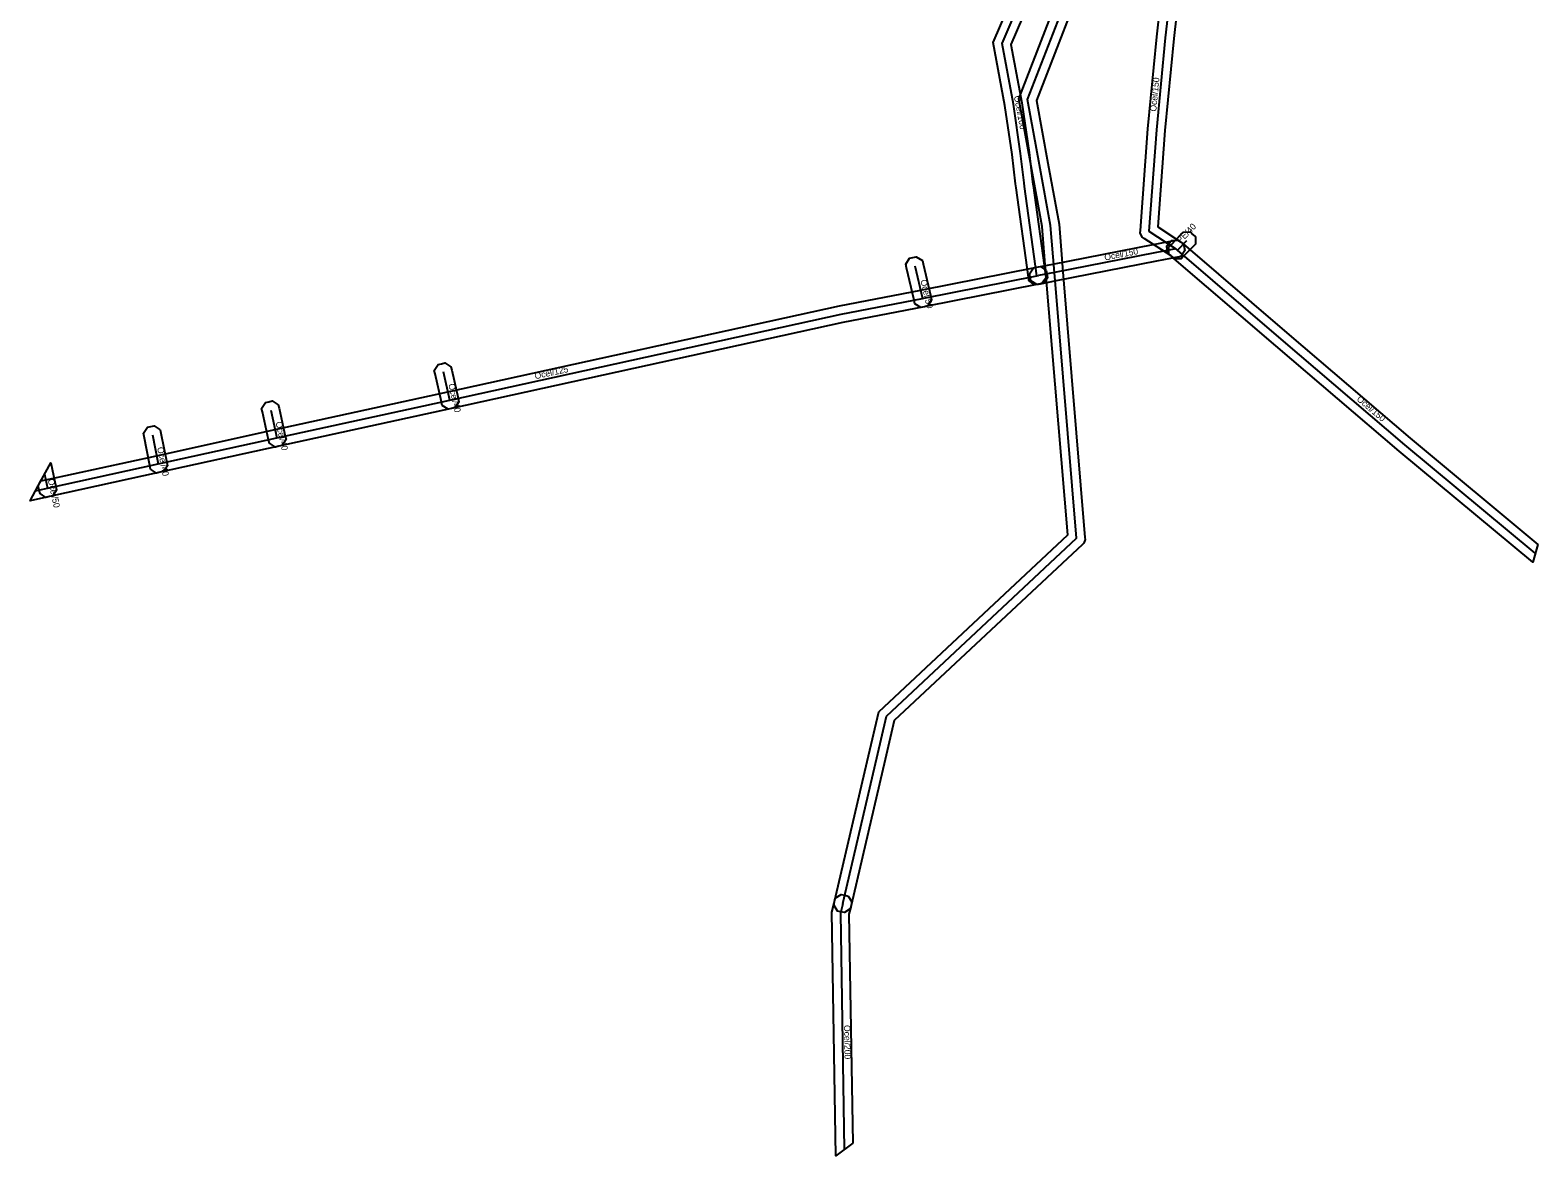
# Model space of a CAD drawing. Extents: x -702919 to -702657, y -1012371 to -1012107.
# Drawn here: x -702887.5 to -702710.5, y -1012371 to -1012238.8 of the extents above; entities that cross this region are included whole.
import ezdxf

# ---------------------------------------------------------------- set-up
doc = ezdxf.new("R2010")
doc.units = 0
for name, color, linetype in [('1', 7, 'Continuous'), ('14', 7, 'Continuous'), ('20', 7, 'Continuous'), ('24', 7, 'Continuous'), ('30', 7, 'Continuous')]:
    doc.layers.add(name, color=color, linetype=linetype)

msp = doc.modelspace()

# ---------------------------------------------------------------- linework, layer by layer
at = {"layer": '1'}
for points in [[(-702762.96, -1012230.4), (-702769.42, -1012247.1), (-702768.08, -1012254.47), (-702766.76, -1012261.63), (-702766.3, -1012267.22), (-702763.71, -1012298.39), (-702763.69, -1012298.62), (-702763.86, -1012299.05), (-702764.02, -1012299.21), (-702786.1, -1012319.9), (-702787.17, -1012324.48), (-702791.17, -1012341.59), (-702791.26, -1012342), (-702791.96, -1012342.44), (-702792.37, -1012342.34), (-702792.77, -1012342.25), (-702793.21, -1012341.54), (-702793.11, -1012341.14), (-702789.12, -1012324.02), (-702787.91, -1012318.85), (-702765.74, -1012298.08), (-702768.29, -1012267.38), (-702768.74, -1012261.89), (-702770.04, -1012254.83), (-702771.48, -1012246.91), (-702764.83, -1012229.68)], [(-702770.32, -1012235.65), (-702772.41, -1012240.53), (-702771.13, -1012247.37), (-702770.28, -1012253.19), (-702769.86, -1012256.65), (-702769.81, -1012257.09), (-702768.36, -1012267.57), (-702768.3, -1012267.98), (-702768.8, -1012268.64), (-702769.21, -1012268.69), (-702769.62, -1012268.75), (-702770.29, -1012268.25), (-702770.34, -1012267.84), (-702771.8, -1012257.34), (-702771.85, -1012256.88), (-702772.26, -1012253.46), (-702773.11, -1012247.7), (-702774.49, -1012240.3), (-702772.15, -1012234.82)]]:
    msp.add_lwpolyline(points, dxfattribs=at)
for points in [[(-702752.25, -1012230.69), (-702752.3, -1012231.1), (-702753.29, -1012239.84), (-702754.33, -1012250.62), (-702755.17, -1012261.94), (-702752.51, -1012263.68), (-702752.16, -1012263.91), (-702751.99, -1012264.72), (-702752.22, -1012265.06), (-702752.45, -1012265.41), (-702753.26, -1012265.58), (-702753.6, -1012265.35), (-702756.76, -1012263.29), (-702756.99, -1012263.14), (-702757.23, -1012262.65), (-702757.21, -1012262.38), (-702756.33, -1012250.45), (-702755.28, -1012239.63), (-702754.28, -1012230.88), (-702754.24, -1012230.46), (-702753.59, -1012229.95), (-702753.18, -1012230), (-702752.77, -1012230.04)], [(-702753.86, -1012264.29), (-702753.57, -1012263.99), (-702752.45, -1012262.84), (-702752.16, -1012262.55), (-702751.33, -1012262.54), (-702751.04, -1012262.83), (-702750.74, -1012263.12), (-702750.73, -1012263.95), (-702751.02, -1012264.24), (-702752.14, -1012265.39), (-702752.43, -1012265.68), (-702753.26, -1012265.69), (-702753.55, -1012265.4), (-702753.85, -1012265.11)], [(-702752.46, -1012265.42), (-702752.86, -1012265.5), (-702755.31, -1012265.97), (-702767.09, -1012268.28), (-702768.97, -1012268.65), (-702769.37, -1012268.72), (-702770.06, -1012268.26), (-702770.14, -1012267.85), (-702770.22, -1012267.45), (-702769.76, -1012266.76), (-702769.35, -1012266.68), (-702767.47, -1012266.32), (-702755.7, -1012264.01), (-702753.25, -1012263.53), (-702752.84, -1012263.45), (-702752.16, -1012263.92), (-702752.08, -1012264.32), (-702752, -1012264.73)], [(-702725.52, -1012286.74), (-702710.54, -1012299.21), (-702711.15, -1012301.31), (-702726.81, -1012288.27), (-702741.31, -1012275.89), (-702753.51, -1012265.45), (-702753.71, -1012265.28), (-702754.02, -1012265.01), (-702754.09, -1012264.18), (-702753.82, -1012263.86), (-702753.55, -1012263.55), (-702752.72, -1012263.49), (-702752.41, -1012263.76), (-702752.2, -1012263.93), (-702740.01, -1012274.37)], [(-702782.8, -1012265.88), (-702782.71, -1012266.28), (-702781.82, -1012270.11), (-702781.72, -1012270.51), (-702782.16, -1012271.21), (-702782.56, -1012271.31), (-702782.97, -1012271.4), (-702783.67, -1012270.96), (-702783.77, -1012270.56), (-702784.66, -1012266.73), (-702784.75, -1012266.33), (-702784.31, -1012265.63), (-702783.91, -1012265.53), (-702783.51, -1012265.44)], [(-702885.29, -1012293.6), (-702887.55, -1012294.1), (-702886.29, -1012291.77), (-702885.72, -1012291.65), (-702872.71, -1012288.8), (-702858.78, -1012285.74), (-702838.5, -1012281.3), (-702792.54, -1012271.22), (-702782.98, -1012269.35), (-702782.83, -1012269.32), (-702769.55, -1012266.72), (-702769.36, -1012266.68), (-702768.95, -1012266.6), (-702768.26, -1012267.06), (-702768.18, -1012267.47), (-702768.1, -1012267.87), (-702768.55, -1012268.56), (-702768.96, -1012268.64), (-702769.16, -1012268.68), (-702782.45, -1012271.29), (-702782.6, -1012271.31), (-702792.13, -1012273.18), (-702838.07, -1012283.25), (-702858.35, -1012287.7), (-702872.29, -1012290.75)], [(-702839.17, -1012282.9), (-702839.26, -1012282.49), (-702840.01, -1012279.19), (-702840.1, -1012278.79), (-702839.66, -1012278.09), (-702839.26, -1012278), (-702838.85, -1012277.91), (-702838.15, -1012278.35), (-702838.06, -1012278.75), (-702837.31, -1012282.05), (-702837.22, -1012282.46), (-702837.66, -1012283.16), (-702838.07, -1012283.25), (-702838.47, -1012283.34)], [(-702858.42, -1012282.82), (-702858.33, -1012283.22), (-702857.59, -1012286.5), (-702857.5, -1012286.91), (-702857.95, -1012287.6), (-702858.35, -1012287.7), (-702858.75, -1012287.79), (-702859.45, -1012287.34), (-702859.55, -1012286.94), (-702860.28, -1012283.66), (-702860.37, -1012283.25), (-702859.93, -1012282.55), (-702859.53, -1012282.46), (-702859.12, -1012282.37)], [(-702872.29, -1012285.75), (-702872.21, -1012286.15), (-702871.52, -1012289.58), (-702871.44, -1012289.98), (-702871.9, -1012290.67), (-702872.3, -1012290.75), (-702872.71, -1012290.84), (-702873.4, -1012290.38), (-702873.48, -1012289.97), (-702874.17, -1012286.55), (-702874.25, -1012286.14), (-702873.79, -1012285.45), (-702873.39, -1012285.37), (-702872.98, -1012285.29)], [(-702886.48, -1012292.84), (-702886.59, -1012292.33), (-702885.13, -1012289.63), (-702884.53, -1012292.41), (-702884.44, -1012292.82), (-702884.89, -1012293.51), (-702885.29, -1012293.6), (-702885.7, -1012293.69), (-702886.39, -1012293.24)], [(-702790.98, -1012369.52), (-702792.96, -1012370.99), (-702793.42, -1012342.38), (-702793.15, -1012341.31), (-702793.11, -1012341.14), (-702793.02, -1012340.74), (-702792.32, -1012340.3), (-702791.91, -1012340.39), (-702791.51, -1012340.49), (-702791.07, -1012341.19), (-702791.17, -1012341.59), (-702791.21, -1012341.78), (-702791.42, -1012342.61)]]:
    msp.add_lwpolyline(points, close=True, dxfattribs=at)
at = {"layer": '14'}
for points in [[(-702769.35, -1012267.7), (-702770.81, -1012257.21), (-702770.85, -1012256.76), (-702771.27, -1012253.33), (-702772.12, -1012247.54), (-702773.45, -1012240.41), (-702771.23, -1012235.23), (-702767.42, -1012227.24)], [(-702753.29, -1012230.99), (-702754.29, -1012239.73), (-702755.33, -1012250.53), (-702756.21, -1012262.45), (-702753.06, -1012264.52)], [(-702753.06, -1012264.52), (-702755.51, -1012264.99), (-702767.28, -1012267.3), (-702769.16, -1012267.66)], [(-702710.85, -1012300.26), (-702726.17, -1012287.51), (-702740.66, -1012275.13), (-702752.85, -1012264.69), (-702753.06, -1012264.52)], [(-702752.85, -1012264.69), (-702751.74, -1012263.54)], [(-702886.92, -1012292.93), (-702885.5, -1012292.62), (-702872.5, -1012289.77), (-702858.57, -1012286.72), (-702838.29, -1012282.27), (-702792.34, -1012272.2), (-702782.79, -1012270.33), (-702782.64, -1012270.3), (-702769.35, -1012267.7), (-702769.16, -1012267.66)], [(-702783.68, -1012266.51), (-702782.79, -1012270.33)], [(-702838.29, -1012282.27), (-702839.03, -1012278.97)], [(-702859.31, -1012283.44), (-702858.57, -1012286.72)], [(-702873.19, -1012286.35), (-702872.5, -1012289.77)], [(-702885.86, -1012290.98), (-702885.5, -1012292.62)]]:
    msp.add_lwpolyline(points, dxfattribs=at)
at = {"layer": '24'}
for points in [[(-702792.14, -1012341.37), (-702788.14, -1012324.25), (-702787, -1012319.38), (-702764.71, -1012298.48), (-702767.29, -1012267.3), (-702767.75, -1012261.76), (-702769.06, -1012254.65), (-702770.45, -1012247), (-702763.89, -1012230.04), (-702755.32, -1012207.88), (-702741.45, -1012177.47), (-702734.96, -1012157.17), (-702731.42, -1012144.07), (-702723.58, -1012109.52), (-702723.11, -1012107.71)], [(-702792.14, -1012341.37), (-702792.18, -1012341.55), (-702792.42, -1012342.5), (-702791.97, -1012370.25)]]:
    msp.add_lwpolyline(points, dxfattribs=at)

# ---------------------------------------------------------------- texts
at = {"layer": '20'}
for s, rotation, p in [('Ocel/150', 84.4948, (-702755.35, -1012248.43)), ('Ocel/100', 280.5721, (-702772.06, -1012246.61)), ('PE/40', 45.6836, (-702752.5, -1012263.92)), ('Ocel/150', 11.0693, (-702761.36, -1012265.9)), ('Ocel/50', 283.1203, (-702783.04, -1012268.22)), ('Ocel/125', 12.3631, (-702828.24, -1012279.83)), ('Ocel/40', 282.7547, (-702838.46, -1012280.42)), ('Ocel/150', 319.5158, (-702731.88, -1012282.26)), ('Ocel/40', 282.6563, (-702858.74, -1012284.88)), ('Ocel/40', 281.3582, (-702872.65, -1012287.86)), ('Ocel/50', 282.212, (-702885.48, -1012291.6))]:
    msp.add_text(s, height=0.75, rotation=rotation, dxfattribs=at).set_placement(p)
at = {"layer": '30'}
msp.add_text('Ocel/200', height=0.75, rotation=270.9294, dxfattribs=at).set_placement((-702792, -1012355.64))

doc.saveas('drawing.dxf')
